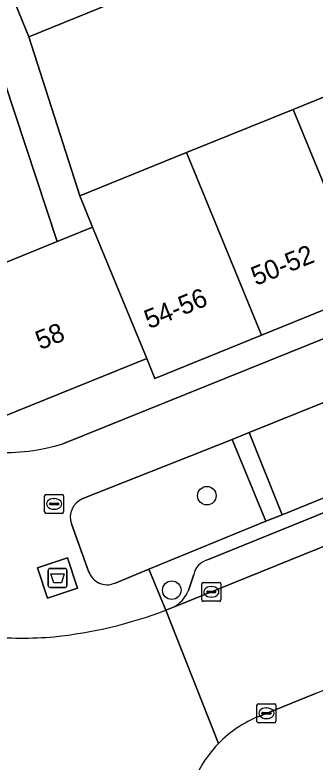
# Model space of a CAD drawing. Extents: x 162989 to 165008, y 383432 to 384338.
# Drawn here: x 163858.12 to 163873.96, y 383958.35 to 383997.76 of the extents above; entities that cross this region are included whole.
import ezdxf

# ---------------------------------------------------------------- set-up
doc = ezdxf.new("R2010")
doc.units = 0
for name, color, linetype in [('IMGEO_Afval_apart_plaats', 7, 'Continuous'), ('IMGEO_Boom', 7, 'Continuous'), ('IMGEO_Erf', 7, 'Continuous'), ('IMGEO_Groenvoorziening', 7, 'Continuous'), ('IMGEO_Kolk', 7, 'Continuous'), ('IMGEO_Pand', 7, 'Continuous'), ('IMGEO_Pand_nummerreeks', 7, 'Continuous'), ('IMGEO_Parkeervlak_open', 7, 'Continuous'), ('IMGEO_Rijbaan_lokaal_open', 7, 'Continuous'), ('IMGEO_Rioolput', 7, 'Continuous'), ('IMGEO_Voetpad_gesloten', 7, 'Continuous'), ('IMGEO_Voetpad_open', 7, 'Continuous')]:
    doc.layers.add(name, color=color, linetype=linetype)

msp = doc.modelspace()

# ---------------------------------------------------------------- linework, layer by layer
at = {"layer": 'IMGEO_Afval_apart_plaats'}
for p, q in [((163859.878, 383967.661), (163859.878, 383968.461)), ((163859.878, 383968.461), (163859.878, 383967.661)), ((163859.978, 383968.561), (163860.768, 383968.561)), ((163860.768, 383968.561), (163859.978, 383968.561)), ((163860.868, 383968.461), (163860.868, 383967.661)), ((163860.868, 383967.661), (163860.868, 383968.461)), ((163860.768, 383967.561), (163859.978, 383967.561)), ((163859.978, 383967.561), (163860.768, 383967.561))]:
    msp.add_line(p, q, dxfattribs=at)
msp.add_lwpolyline([(163860.021, 383968.275), (163860.725, 383968.275), (163860.576, 383967.805), (163860.17, 383967.805), (163860.021, 383968.275)], dxfattribs=at)
for centre, start, end in [((163859.978, 383968.461), 90, 180), ((163859.978, 383968.461), 90, 180), ((163860.768, 383968.461), 0, 90), ((163860.768, 383968.461), 360, 90), ((163859.978, 383967.661), 180, 270), ((163859.978, 383967.661), 180, 270), ((163860.768, 383967.661), 270, 0), ((163860.768, 383967.661), 270, 0)]:
    msp.add_arc(centre, 0.1, start, end, dxfattribs=at)
at = {"layer": 'IMGEO_Boom'}
for centre in [(163868.251, 383972.399), (163866.4, 383967.415)]:
    msp.add_circle(centre, 0.489, dxfattribs=at)
at = {"layer": 'IMGEO_Erf'}
for points in [[(163860.657, 383975.132), (163922.286, 384000), (163935.54, 384005.348), (163935.283, 384006.035), (163927.294, 384027.344)], [(163863.146, 383998.341), (163858.852, 383996.609), (163861.551, 383988.223), (163867.173, 383990.498), (163872.805, 383992.776), (163878.436, 383995.055), (163883.712, 383997.189), (163883.071, 383998.773)], [(163906.07, 383995.217), (163900.474, 383992.948), (163899.978, 383994.175), (163893.721, 383991.644), (163887.464, 383989.112), (163888.034, 383987.703), (163882.402, 383985.424), (163876.771, 383983.146), (163871.139, 383980.867), (163865.501, 383978.586), (163865.079, 383979.629), (163857.441, 383976.539)], [(163857.591, 383984.685), (163860.357, 383985.804), (163857.577, 383994.229)]]:
    msp.add_lwpolyline(points, dxfattribs=at)
msp.add_arc((163857.638, 383984.984), 10.304, 246.1749, 287.0351, dxfattribs=at)
at = {"layer": 'IMGEO_Groenvoorziening'}
msp.add_lwpolyline([(163872.224, 383971.398), (163891.415, 383979.207), (163889.739, 383983.483), (163870.491, 383975.736)], close=True, dxfattribs=at)
for points in [[(163869.582, 383975.37), (163861.708, 383972.246)], [(163863.369, 383967.776), (163865.192, 383968.522), (163871.367, 383971.048), (163869.582, 383975.37)], [(163861.108, 383970.913), (163862.027, 383968.371)]]:
    msp.add_lwpolyline(points, dxfattribs=at)
for centre, radius, start, end in [((163862.096, 383971.27), 1.05, 111.6627, 199.8711), ((163862.984, 383968.719), 1.018, 199.9686, 292.2094)]:
    msp.add_arc(centre, radius, start, end, dxfattribs=at)
at = {"layer": 'IMGEO_Kolk'}
for p, q in [((163867.987, 383966.901), (163867.987, 383967.753)), ((163868.062, 383967.827), (163868.914, 383967.827)), ((163868.988, 383967.753), (163868.988, 383966.901)), ((163868.246, 383967.321), (163868.246, 383967.333)), ((163868.684, 383967.284), (163868.286, 383967.284)), ((163868.289, 383967.37), (163868.687, 383967.37)), ((163868.475, 383967.607), (163868.5, 383967.607)), ((163868.73, 383967.333), (163868.73, 383967.321)), ((163868.498, 383967.047), (163868.473, 383967.047)), ((163868.914, 383966.827), (163868.062, 383966.827)), ((163870.896, 383960.496), (163870.896, 383961.348)), ((163870.971, 383961.422), (163871.823, 383961.422)), ((163871.897, 383961.348), (163871.897, 383960.496)), ((163871.198, 383960.965), (163871.596, 383960.965)), ((163871.384, 383961.202), (163871.409, 383961.202)), ((163871.155, 383960.916), (163871.155, 383960.928)), ((163871.593, 383960.879), (163871.195, 383960.879)), ((163871.407, 383960.642), (163871.382, 383960.642)), ((163871.639, 383960.928), (163871.639, 383960.916)), ((163871.823, 383960.422), (163870.971, 383960.422))]:
    msp.add_line(p, q, dxfattribs=at)
for points in [[(163867.987, 383966.901), (163867.987, 383967.753)], [(163868.062, 383967.827), (163868.914, 383967.827)], [(163868.988, 383967.753), (163868.988, 383966.901)], [(163868.914, 383966.827), (163868.062, 383966.827)], [(163870.896, 383960.496), (163870.896, 383961.348)], [(163870.971, 383961.422), (163871.823, 383961.422)], [(163871.897, 383961.348), (163871.897, 383960.496)], [(163871.823, 383960.422), (163870.971, 383960.422)]]:
    msp.add_lwpolyline(points, dxfattribs=at)
for centre, radius, start, end in [((163868.064, 383967.751), 0.0765, 91.552, 178.448), ((163868.064, 383967.751), 0.0765, 91.552, 178.448), ((163868.912, 383967.751), 0.0765, 1.552, 88.448), ((163868.912, 383967.751), 0.0765, 1.552, 88.448), ((163868.286, 383967.33), 0.0403, 85.8775, 175.7526), ((163868.283, 383967.32), 0.0366, 178.938, 274.7102), ((163868.687, 383967.327), 0.043, 264.8664, 352.4533), ((163868.691, 383967.332), 0.0386, 1.7309, 96.639), ((163868.064, 383966.903), 0.0765, 181.552, 268.448), ((163868.064, 383966.903), 0.0765, 181.552, 268.448), ((163868.912, 383966.903), 0.0765, 271.552, 358.448), ((163868.912, 383966.903), 0.0765, 271.552, 358.448), ((163870.973, 383961.346), 0.0765, 91.552, 178.448), ((163870.973, 383961.346), 0.0765, 91.552, 178.448), ((163871.821, 383961.346), 0.0765, 1.552, 88.448), ((163871.821, 383961.346), 0.0765, 1.552, 88.448), ((163871.195, 383960.925), 0.0403, 85.8775, 175.7526), ((163871.6, 383960.927), 0.0386, 1.7309, 96.639), ((163871.192, 383960.915), 0.0366, 178.938, 274.7102), ((163871.596, 383960.922), 0.043, 264.8664, 352.4533), ((163870.973, 383960.498), 0.0765, 181.552, 268.448), ((163870.973, 383960.498), 0.0765, 181.552, 268.448), ((163871.821, 383960.498), 0.0765, 271.552, 358.448), ((163871.821, 383960.498), 0.0765, 271.552, 358.448)]:
    msp.add_arc(centre, radius, start, end, dxfattribs=at)
for centre, major_axis, ratio, start_param, end_param in [((163868.474, 383967.327), (-0.387, 0.002), 0.722429, 4.712389, 7.853982), ((163868.499, 383967.327), (-0.39, 0.002), 0.717154, 1.570796, 4.712389), ((163871.383, 383960.922), (-0.387, 0.002), 0.722429, 4.712389, 7.853982), ((163871.408, 383960.922), (-0.39, 0.002), 0.717154, 1.570796, 4.712389)]:
    msp.add_ellipse(centre, major_axis=major_axis, ratio=ratio, start_param=start_param, end_param=end_param, dxfattribs=at)
at = {"layer": 'IMGEO_Pand'}
for points in [[(163858.852, 383996.609), (163863.146, 383998.341), (163862.475, 384000), (163862.092, 384000.947), (163859.746, 384000), (163857.798, 383999.214)], [(163878.436, 383995.055), (163872.805, 383992.776), (163876.771, 383983.146), (163882.402, 383985.424)], [(163867.173, 383990.498), (163871.139, 383980.867), (163876.771, 383983.146), (163872.805, 383992.776)], [(163862.225, 383986.559), (163865.079, 383979.629), (163865.501, 383978.586), (163871.139, 383980.867), (163867.173, 383990.498), (163861.551, 383988.223)], [(163862.225, 383986.559), (163860.357, 383985.804), (163857.591, 383984.685), (163853.71, 383986.483), (163850.496, 383979.756), (163857.441, 383976.539), (163865.079, 383979.629)]]:
    msp.add_lwpolyline(points, close=True, dxfattribs=at)
at = {"layer": 'IMGEO_Parkeervlak_open'}
for points in [[(163899.909, 383981.843), (163868.281, 383969.012)], [(163866.484, 383966.516), (163902.71, 383981.172)], [(163867.56, 383968.247), (163867.284, 383967.396)]]:
    msp.add_lwpolyline(points, dxfattribs=at)
for centre, radius, start, end in [((163868.576, 383968.012), 1.043, 106.4206, 166.9714), ((163865.6, 383968.123), 1.834, 298.8059, 336.6468)]:
    msp.add_arc(centre, radius, start, end, dxfattribs=at)
at = {"layer": 'IMGEO_Rijbaan_lokaal_open'}
for points in [[(163899.148, 383972.197), (163900.176, 383972.615), (163900.336, 383972.68), (163903.835, 383974.102), (163903.966, 383974.155), (163905.486, 383974.773), (163902.862, 383981.233), (163902.71, 383981.172), (163866.484, 383966.516), (163866.224, 383966.406), (163866.079, 383966.355), (163868.869, 383959.329)], [(163870.987, 383960.755), (163873.978, 383961.971), (163875.885, 383962.746), (163899.148, 383972.197)], [(163868.869, 383959.329), (163866.079, 383966.355)]]:
    msp.add_lwpolyline(points, dxfattribs=at)
for centre, radius, start, end in [((163857.714, 383988.49), 23.663, 276.0313, 290.7028), ((163858.496, 383985.901), 21.012, 264.8074, 274.6523), ((163873.361, 383954.944), 6.278, 112.2175, 135.6855), ((163873.38, 383954.926), 6.303, 135.6971, 168.7888)]:
    msp.add_arc(centre, radius, start, end, dxfattribs=at)
at = {"layer": 'IMGEO_Rioolput'}
for p, q in [((163859.691, 383971.54), (163859.691, 383972.392)), ((163859.766, 383972.466), (163860.618, 383972.466)), ((163860.692, 383972.392), (163860.692, 383971.54)), ((163859.993, 383972.009), (163860.391, 383972.009)), ((163860.179, 383972.246), (163860.204, 383972.246)), ((163859.95, 383971.96), (163859.95, 383971.972)), ((163860.388, 383971.923), (163859.99, 383971.923)), ((163860.202, 383971.686), (163860.177, 383971.686)), ((163860.434, 383971.972), (163860.434, 383971.96)), ((163860.618, 383971.466), (163859.766, 383971.466))]:
    msp.add_line(p, q, dxfattribs=at)
for points in [[(163859.691, 383971.54), (163859.691, 383972.392)], [(163859.766, 383972.466), (163860.618, 383972.466)], [(163860.692, 383972.392), (163860.692, 383971.54)], [(163860.618, 383971.466), (163859.766, 383971.466)]]:
    msp.add_lwpolyline(points, dxfattribs=at)
for centre, radius, start, end in [((163859.768, 383972.39), 0.0765, 91.552, 178.448), ((163859.768, 383972.39), 0.0765, 91.552, 178.448), ((163860.616, 383972.39), 0.0765, 1.552, 88.448), ((163860.616, 383972.39), 0.0765, 1.552, 88.448), ((163859.99, 383971.969), 0.0403, 85.8775, 175.7526), ((163860.395, 383971.971), 0.0386, 1.7309, 96.639), ((163859.987, 383971.959), 0.0366, 178.938, 274.7102), ((163860.391, 383971.966), 0.043, 264.8664, 352.4533), ((163859.768, 383971.542), 0.0765, 181.552, 268.448), ((163859.768, 383971.542), 0.0765, 181.552, 268.448), ((163860.616, 383971.542), 0.0765, 271.552, 358.448), ((163860.616, 383971.542), 0.0765, 271.552, 358.448)]:
    msp.add_arc(centre, radius, start, end, dxfattribs=at)
for centre, major_axis, ratio, start_param, end_param in [((163860.178, 383971.966), (-0.387, 0.002), 0.722429, 4.712389, 7.853982), ((163860.203, 383971.966), (-0.39, 0.002), 0.717154, 1.570796, 4.712389)]:
    msp.add_ellipse(centre, major_axis=major_axis, ratio=ratio, start_param=start_param, end_param=end_param, dxfattribs=at)
at = {"layer": 'IMGEO_Voetpad_gesloten'}
msp.add_lwpolyline([(163860.9, 383969.124), (163859.312, 383968.593), (163859.846, 383966.997), (163861.434, 383967.528)], close=True, dxfattribs=at)
at = {"layer": 'IMGEO_Voetpad_open'}
for points in [[(163857.577, 383994.229), (163860.357, 383985.804), (163862.225, 383986.559), (163861.551, 383988.223), (163858.852, 383996.609), (163857.798, 383999.214), (163859.746, 384000), (163862.092, 384000.947), (163863.492, 384001.512), (163868.392, 384003.49), (163873.22, 384005.438), (163874.611, 384006), (163879.788, 384008.089), (163884.385, 384009.944), (163885.785, 384010.509), (163890.765, 384012.519), (163892.18, 384013.09), (163897.293, 384015.166), (163898.746, 384015.746), (163903.482, 384017.669), (163908.4, 384019.665)], [(163939.919, 384003.04), (163938.767, 384006.115), (163937.352, 384005.559), (163937.132, 384006.117), (163938.547, 384006.674), (163938.328, 384007.232), (163936.28, 384006.427), (163935.283, 384006.035), (163935.54, 384005.348), (163922.286, 384000), (163860.657, 383975.132)], [(163861.708, 383972.246), (163869.582, 383975.37), (163870.491, 383975.736), (163889.739, 383983.483), (163890.546, 383983.807), (163899.886, 383987.554), (163904.39, 383989.379), (163912.57, 383992.705), (163913.546, 383993.102), (163929.686, 383999.636), (163930.666, 383999.968), (163938.946, 384003.453)], [(163943.911, 383999.998), (163944.428, 384001.499), (163941.121, 384000), (163940.918, 383999.359), (163932.321, 383995.796), (163931.364, 383995.406), (163915.242, 383988.827), (163914.265, 383988.432), (163905.625, 383984.998), (163901.827, 383983.48), (163892.281, 383979.552), (163891.415, 383979.207), (163872.224, 383971.398), (163871.367, 383971.048), (163865.192, 383968.522), (163866.079, 383966.355), (163866.224, 383966.406), (163866.484, 383966.516)], [(163868.281, 383969.012), (163899.909, 383981.843)], [(163862.027, 383968.371), (163861.108, 383970.913)], [(163866.079, 383966.355), (163865.192, 383968.522), (163863.369, 383967.776)], [(163867.284, 383967.396), (163867.56, 383968.247)], [(163873.978, 383961.971), (163870.987, 383960.755)]]:
    msp.add_lwpolyline(points, dxfattribs=at)
for points in [[(163870.491, 383975.736), (163869.582, 383975.37), (163871.367, 383971.048), (163872.224, 383971.398)], [(163860.9, 383969.124), (163861.434, 383967.528), (163859.846, 383966.997), (163859.312, 383968.593)]]:
    msp.add_lwpolyline(points, close=True, dxfattribs=at)
for centre, radius, start, end in [((163857.638, 383984.984), 10.304, 246.1749, 287.0351), ((163862.096, 383971.27), 1.05, 111.6627, 199.8711), ((163868.576, 383968.012), 1.043, 106.4206, 166.9714), ((163862.984, 383968.719), 1.018, 199.9686, 292.2094), ((163865.6, 383968.123), 1.834, 298.8059, 336.6468), ((163857.714, 383988.49), 23.663, 276.0313, 290.7028), ((163858.496, 383985.901), 21.012, 264.8074, 274.6523), ((163873.361, 383954.944), 6.278, 112.2175, 135.6855), ((163873.38, 383954.926), 6.303, 135.6971, 168.7888)]:
    msp.add_arc(centre, radius, start, end, dxfattribs=at)

# ---------------------------------------------------------------- texts
at = {"layer": 'IMGEO_Pand_nummerreeks'}
for s, rotation, p in [('50-52', 22.0286, (163870.834, 383983.462)), ('54-56', 22.0286, (163865.2, 383981.182)), ('58', 22.0245, (163859.461, 383980.075))]:
    msp.add_text(s, height=1, rotation=rotation, dxfattribs=at).set_placement(p)

doc.saveas('drawing.dxf')
